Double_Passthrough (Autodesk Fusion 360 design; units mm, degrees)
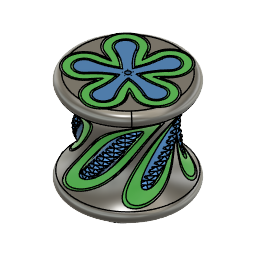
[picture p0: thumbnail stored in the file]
sketch "Sketch1" plane through (0, 0, 0) normal (0, 1, 0) x axis (1, 0, 0)
  line L1 (0, 12.7) -> (0, 0)
  circle C1 centre (0, 0) radius 25.4
  arc A1 centre (0, 12.7) radius 3.175 clockwise from (-2.8708, 11.3439) to (2.8708, 11.3439)
  arc A2 centre (0, 0) radius 1.5875 clockwise from (1.5159, 0.4713) to (-1.5159, 0.4713)
  arc A3 centre (0, 12.7) radius 6.35 clockwise from (-5.7771, 10.0641) to (5.7771, 10.0641)
  arc A4 centre (-12.0784, 3.9245) radius 6.35 clockwise from (-11.3567, -2.3843) to (-7.7863, 8.6043)
  arc A5 centre (-12.0784, 3.9245) radius 3.175 clockwise from (-11.6758, 0.7751) to (-9.9015, 6.2358)
  arc A6 centre (0, 0) radius 1.5875 clockwise from (0.0202, 1.5874) to (-0.9167, -1.2961)
  arc A7 centre (-7.4649, -10.2745) radius 6.35 clockwise from (-1.2418, -11.5377) to (-10.5893, -4.7464)
  arc A8 centre (-7.4649, -10.2745) radius 3.175 clockwise from (-4.3452, -10.8648) to (-8.9903, -7.49)
  arc A9 centre (0, 0) radius 1.5875 clockwise from (-1.5034, 0.5098) to (0.9494, -1.2723)
  arc A10 centre (7.4649, -10.2745) radius 6.35 clockwise from (10.5893, -4.7464) to (1.2418, -11.5377)
  arc A11 centre (7.4649, -10.2745) radius 3.175 clockwise from (8.9903, -7.49) to (4.3452, -10.8648)
  arc A12 centre (0, 0) radius 1.5875 clockwise from (-0.9494, -1.2723) to (1.5034, 0.5098)
  arc A13 centre (12.0784, 3.9245) radius 6.35 clockwise from (7.7863, 8.6043) to (11.3567, -2.3843)
  arc A14 centre (12.0784, 3.9245) radius 3.175 clockwise from (9.9015, 6.2358) to (11.6758, 0.7751)
  arc A15 centre (0, 0) radius 1.5875 clockwise from (0.9167, -1.2961) to (-0.0202, 1.5874)
  arc A16 centre (-15.2253, 35.1533) radius 35.1338 clockwise from (8.0136, 8.803) to (4.337, 5.9694)
  arc A17 centre (38.1376, -3.6172) radius 35.1338 clockwise from (4.337, 5.9694) to (5.8958, 10.3417)
  arc A18 centre (15.2253, 35.1533) radius 35.1338 clockwise from (-4.337, 5.9694) to (-8.0136, 8.803)
  arc A19 centre (-38.1376, -3.6172) radius 35.1338 clockwise from (-5.8958, 10.3417) to (-4.337, 5.9694)
  arc A20 centre (-28.7279, 25.3431) radius 35.1338 clockwise from (-7.0175, -2.2801) to (-10.8485, -4.9011)
  arc A21 centre (-8.3451, -37.3888) radius 35.1338 clockwise from (-11.6574, -2.4115) to (-7.0175, -2.2801)
  arc A22 centre (-32.9801, -19.4904) radius 35.1338 clockwise from (0, -7.3786) to (1.3089, -11.8321)
  arc A23 centre (32.9801, -19.4904) radius 35.1338 clockwise from (-1.3089, -11.8321) to (0, -7.3786)
  arc A24 centre (8.3451, -37.3888) radius 35.1338 clockwise from (7.0175, -2.2801) to (11.6574, -2.4115)
  arc A25 centre (28.7279, 25.3431) radius 35.1338 clockwise from (10.8485, -4.9011) to (7.0175, -2.2801)
  arc A26 centre (0, 0) radius 3.175 clockwise from (2.8074, -1.483) to (2.7334, -1.6153)
  arc A27 centre (0, 0) radius 3.175 clockwise from (3.1608, -0.2998) to (3.1429, -0.4503)
  arc A28 centre (0, 0) radius 3.175 clockwise from (1.2619, 2.9135) to (1.3995, 2.8499)
  arc A29 centre (0, 0) radius 3.175 clockwise from (-2.3809, 2.1004) to (-2.278, 2.2117)
  arc A30 centre (0, 0) radius 3.175 clockwise from (-1.3995, 2.8499) to (-1.2619, 2.9135)
  arc A31 centre (0, 0) radius 3.175 clockwise from (2.278, 2.2117) to (2.3809, 2.1004)
  arc A32 centre (0, 0) radius 3.175 clockwise from (-2.7334, -1.6153) to (-2.8074, -1.483)
  arc A33 centre (0, 0) radius 3.175 clockwise from (-3.1429, -0.4503) to (-3.1608, -0.2998)
  arc A34 centre (0, 0) radius 3.175 clockwise from (-0.5429, -3.1282) to (-0.6916, -3.0988)
  arc A35 centre (0, 0) radius 3.175 clockwise from (0.6916, -3.0988) to (0.5429, -3.1282)
  arc A36 centre (23.0988, 13.2173) radius 25.0568 clockwise from (1.5139, 0.4919) to (1.5034, 0.5098)
  arc A37 centre (23.0988, 13.2173) radius 25.0568 clockwise from (8.9903, -7.49) to (2.2926, -0.7449)
  arc A38 centre (10.9184, -24.2702) radius 25.0568 clockwise from (2.2926, -0.7449) to (11.6758, 0.7751)
  arc A39 centre (10.9184, -24.2702) radius 25.0568 clockwise from (0.9167, -1.2961) to (0.9357, -1.2878)
  arc A40 centre (19.7084, -17.8839) radius 25.0568 clockwise from (0.9357, -1.2878) to (0.9494, -1.2723)
  arc A41 centre (19.7084, -17.8839) radius 25.0568 clockwise from (-4.3452, -10.8648) to (0, -2.4106)
  arc A42 centre (-19.7084, -17.8839) radius 25.0568 clockwise from (0, -2.4106) to (4.3452, -10.8648)
  arc A43 centre (-19.7084, -17.8839) radius 25.0568 clockwise from (-0.9494, -1.2723) to (-0.9357, -1.2878)
  arc A44 centre (-10.9184, -24.2702) radius 25.0568 clockwise from (-0.9357, -1.2878) to (-0.9167, -1.2961)
  arc A45 centre (-10.9184, -24.2702) radius 25.0568 clockwise from (-11.6758, 0.7751) to (-2.2926, -0.7449)
  arc A46 centre (-23.0988, 13.2173) radius 25.0568 clockwise from (-2.2926, -0.7449) to (-8.9903, -7.49)
  arc A47 centre (-23.0988, 13.2173) radius 25.0568 clockwise from (-1.5034, 0.5098) to (-1.5139, 0.4919)
  arc A48 centre (-26.4563, 2.8841) radius 25.0568 clockwise from (-1.5139, 0.4919) to (-1.5159, 0.4713)
  arc A49 centre (-26.4563, 2.8841) radius 25.0568 clockwise from (-2.8708, 11.3439) to (-1.4169, 1.9502)
  arc A50 centre (5.4325, 26.0526) radius 25.0568 clockwise from (-1.4169, 1.9502) to (-9.9015, 6.2358)
  arc A51 centre (5.4325, 26.0526) radius 25.0568 clockwise from (0.0202, 1.5874) to (0, 1.5919)
  arc A52 centre (-5.4325, 26.0526) radius 25.0568 clockwise from (0, 1.5919) to (-0.0202, 1.5874)
  arc A53 centre (-5.4325, 26.0526) radius 25.0568 clockwise from (9.9015, 6.2358) to (1.4169, 1.9502)
  arc A54 centre (26.4563, 2.8841) radius 25.0568 clockwise from (1.4169, 1.9502) to (2.8708, 11.3439)
  arc A55 centre (26.4563, 2.8841) radius 25.0568 clockwise from (1.5159, 0.4713) to (1.5139, 0.4919)
  arc A56 centre (12.0784, 3.9245) radius 3.81 clockwise from (9.4898, 6.7201) to (11.6274, 0.1413)
  arc A57 centre (-5.4325, 26.0526) radius 24.4218 clockwise from (9.4898, 6.7201) to (2.0346, 2.8004)
  arc A58 centre (26.4563, 2.8841) radius 24.4218 clockwise from (2.0346, 2.8004) to (3.4587, 11.102)
  arc A59 centre (0, 12.7) radius 3.81 clockwise from (-3.4587, 11.102) to (3.4587, 11.102)
  arc A60 centre (-26.4563, 2.8841) radius 24.4218 clockwise from (-3.4587, 11.102) to (-2.0346, 2.8004)
  arc A61 centre (5.4325, 26.0526) radius 24.4218 clockwise from (-2.0346, 2.8004) to (-9.4898, 6.7201)
  arc A62 centre (-12.0784, 3.9245) radius 3.81 clockwise from (-11.6274, 0.1413) to (-9.4898, 6.7201)
  arc A63 centre (-10.9184, -24.2702) radius 24.4218 clockwise from (-11.6274, 0.1413) to (-3.2921, -1.0697)
  arc A64 centre (-23.0988, 13.2173) radius 24.4218 clockwise from (-3.2921, -1.0697) to (-9.3237, -6.9488)
  arc A65 centre (-7.4649, -10.2745) radius 3.81 clockwise from (-3.7275, -11.0147) to (-9.3237, -6.9488)
  arc A66 centre (19.7084, -17.8839) radius 24.4218 clockwise from (-3.7275, -11.0147) to (0, -3.4615)
  arc A67 centre (-19.7084, -17.8839) radius 24.4218 clockwise from (0, -3.4615) to (3.7275, -11.0147)
  arc A68 centre (7.4649, -10.2745) radius 3.81 clockwise from (9.3237, -6.9488) to (3.7275, -11.0147)
  arc A69 centre (23.0988, 13.2173) radius 24.4218 clockwise from (9.3237, -6.9488) to (3.2921, -1.0697)
  arc A70 centre (10.9184, -24.2702) radius 24.4218 clockwise from (3.2921, -1.0697) to (11.6274, 0.1413)
  arc A71 centre (38.1376, -3.6172) radius 34.4988 clockwise from (5.5059, 7.5782) to (6.4786, 10.0894)
  arc A72 centre (-15.2253, 35.1533) radius 34.4988 clockwise from (7.5936, 9.2793) to (5.5059, 7.5782)
  arc A73 centre (12.0784, 3.9245) radius 6.985 clockwise from (7.3571, 9.0723) to (11.2846, -3.0152)
  arc A74 centre (8.3451, -37.3888) radius 34.4988 clockwise from (8.9087, -2.8946) to (11.5976, -3.0437)
  arc A75 centre (28.7279, 25.3431) radius 34.4988 clockwise from (11.1717, -4.3545) to (8.9087, -2.8946)
  arc A76 centre (15.2253, 35.1533) radius 34.4988 clockwise from (-5.5059, 7.5782) to (-7.5936, 9.2793)
  arc A77 centre (-38.1376, -3.6172) radius 34.4988 clockwise from (-6.4786, 10.0894) to (-5.5059, 7.5782)
  arc A78 centre (-28.7279, 25.3431) radius 34.4988 clockwise from (-8.9087, -2.8946) to (-11.1717, -4.3545)
  arc A79 centre (-8.3451, -37.3888) radius 34.4988 clockwise from (-11.5976, -3.0437) to (-8.9087, -2.8946)
  arc A80 centre (-32.9801, -19.4904) radius 34.4988 clockwise from (0, -9.3672) to (0.6891, -11.9705)
  arc A81 centre (32.9801, -19.4904) radius 34.4988 clockwise from (-0.6891, -11.9705) to (0, -9.3672)
  arc A82 centre (-12.0784, 3.9245) radius 6.985 clockwise from (-11.2846, -3.0152) to (-7.3571, 9.0723)
  arc A83 centre (0, 12.7) radius 6.985 clockwise from (-6.3548, 9.8005) to (6.3548, 9.8005)
  arc A84 centre (-7.4649, -10.2745) radius 6.985 clockwise from (-0.6195, -11.664) to (-10.9017, -4.1935)
  arc A85 centre (7.4649, -10.2745) radius 6.985 clockwise from (10.9017, -4.1935) to (0.6195, -11.664)
  arc A86 centre (0, 0) radius 0.9525 clockwise from (-0.5232, -0.7959) to (-0.5953, -0.7436)
  arc A87 centre (0, 0) radius 0.9525 clockwise from (-0.5953, -0.7436) to (-0.9187, 0.2516)
  arc A88 centre (0, 0) radius 0.9525 clockwise from (-0.9187, 0.2516) to (-0.8911, 0.3364)
  arc A89 centre (0, 0) radius 0.9525 clockwise from (-0.8911, 0.3364) to (-0.0445, 0.9515)
  arc A90 centre (0, 0) radius 0.9525 clockwise from (-0.0445, 0.9515) to (0.0445, 0.9515)
  arc A91 centre (0, 0) radius 0.9525 clockwise from (0.0445, 0.9515) to (0.8911, 0.3364)
  arc A92 centre (0, 0) radius 0.9525 clockwise from (0.8911, 0.3364) to (0.9187, 0.2516)
  arc A93 centre (0, 0) radius 0.9525 clockwise from (0.9187, 0.2516) to (0.5953, -0.7436)
  arc A94 centre (0, 0) radius 0.9525 clockwise from (0.5953, -0.7436) to (0.5232, -0.7959)
  arc A95 centre (0, 0) radius 0.9525 clockwise from (0.5232, -0.7959) to (-0.5232, -0.7959)
  point P1 (0, 0)
  point P2 (0, 0)
  point P3 (0, 0)
  point P4 (0, 12.7)
  point P5 (0, 12.7)
  point P8 (5.8958, 10.3417)
  point P18 (-5.8958, 10.3417)
  point P9 (3.1608, -0.2998)
  point P19 (-3.1608, -0.2998)
  point P12 (2.8708, 11.3439)
  point P17 (-2.8708, 11.3439)
  point P13 (1.5159, 0.4713)
  point P15 (-1.5159, 0.4713)
  point P21 (5.7771, 10.0641)
  point P100 (2.8074, -1.483)
  point P101 (3.1429, -0.4503)
  point P103 (2.278, 2.2117)
  point P104 (1.3995, 2.8499)
  point P106 (-1.3995, 2.8499)
  point P107 (-2.278, 2.2117)
  point P109 (-3.1429, -0.4503)
  point P110 (-2.8074, -1.483)
  point P112 (-0.5429, -3.1282)
  point P113 (0.5429, -3.1282)
  point P115 (1.5139, 0.4919)
  point P130 (0, 1.5919)
  coincident P1 P2
  coincident P1 P3
  vertical L1
  coincident P4 P5
  concentric A1 A3
  concentric C1 A33
  tangent A17 A33
  coincident P8 A3
  concentric C1 A2
  symmetric L1 P8 P18
  symmetric L1 P9 P19
  symmetric L1 P12 P17
  symmetric L1 P13 P15
  symmetric L1 A48 A54
  coincident P21 A17
  coincident P100 A36
  coincident P101 A38
  concentric A27 A33
  coincident P103 A52
  coincident P104 A54
  coincident P106 A48
  coincident P107 A50
  coincident P109 A44
  coincident P110 A46
  coincident P112 A40
  coincident P113 A42
  coincident P115 A54
  concentric A36 A37
  concentric A38 A39
  concentric A40 A41
  concentric A42 A43
  concentric A44 A45
  concentric A46 A47
  concentric A48 A49
  coincident L1 P130
  concentric A50 A51
  concentric A52 A53
  concentric A54 A55
  dimension "d1" diameter C1 = 50.8
  dimension "d2" distance P3 P4 = 12.7
  dimension "d3" diameter A3 = 12.7
  dimension "d4" diameter A1 = 6.35
  dimension "d5" diameter A33 = 6.35
  dimension "d6" diameter A2 = 3.175
  dimension "d9" = -0.635
  dimension "d10" = -0.635
  dimension "d11" = 0.635
  dimension "d12" = -0.635
  dimension "d13" = -0.635
  dimension "d14" = -0.635
  dimension "d15" = -0.635
  dimension "d16" = 0.635
  dimension "d17" = 0.635
  dimension "d18" = 0.635
  dimension "d19" = 0.635
  dimension "d20" = -0.635
sketch "Sketch2" plane through (0, 0, 0) normal (0, 0, 1) x axis (1, 0, 0)
  line L1 (0, 38.1) -> (0, 0)
  point P1 (0, 0)
  point P2 (0, 0)
  point P3 (0, 38.1)
  coincident P1 P2
  vertical L1
  dimension "d21" distance P2 P3 = 38.1
sweep "Sweep1" sketch "Sketch1" TwistAngle 120 TaperAngle 0 bodies "Inner"
sweep "Sweep2" sketch "Sketch1" TwistAngle 120 TaperAngle 0 bodies "Middle"
sweep "Sweep3" sketch "Sketch1" TwistAngle 120 TaperAngle 0 bodies "Outer"
sketch "Sketch3" plane through (0, 0, 0) normal (0, 0, 1) x axis (1, 0, 0)
  line L1 (25.4, 19.05) -> (25.4, 0)
  circle C1 centre (32.5845, 19.05) radius 19.05
  point P2 (25.4, 0)
  point P3 (25.4, 19.05)
  vertical L1
  dimension "d40" distance P2 P3 = 19.05
  dimension "d41" diameter C1 = 38.1
revolve "Revolve2" sketch "Sketch3" AlongAngle 360
fillet "Fillet1" radius 2.54
sketch "Sketch4" plane through (0, 0, 0) normal (0, 0, 1) x axis (1, 0, 0)
  line L1 (0, 30.48) -> (0, 7.62)
  vertical L1
work_plane "WorkPlane1" AlongDistance 7.62
coil_primitive "CoilPrimitive1" Diameter 31.75 SectionSize 1.27 TaperAngle 0 Height 22.86
mirror "Mirror1" mirrorStitchTolerance 0.1016
circular_pattern "C-Pattern1" countU 15 TotalAngle 360
named bodies: "Inner", "Middle", "Outer"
